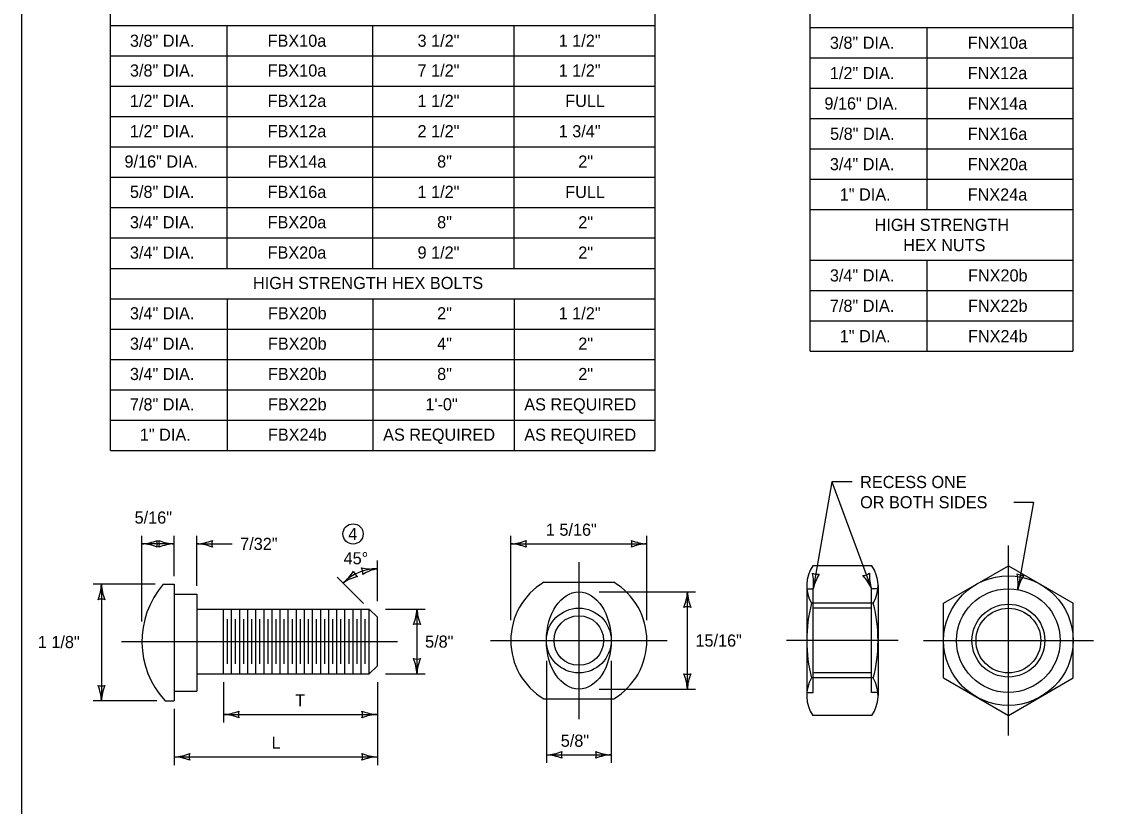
# Model space of a CAD drawing. Extents: x 49991.4 to 50021, y 49987.6 to 50011.4.
# Drawn here: x 49999.38 to 50004.77, y 49992.68 to 49996.55 of the extents above; entities that cross this region are included whole.
import ezdxf

# ---------------------------------------------------------------- set-up
doc = ezdxf.new("R2010")
doc.units = 0
for name, color, linetype in [('Level 1', 7, 'Continuous'), ('Level 2', 7, 'Continuous'), ('Level 3', 7, 'Continuous'), ('Level 4', 7, 'Continuous'), ('Level 5', 7, 'Continuous')]:
    doc.layers.add(name, color=color, linetype=linetype)

msp = doc.modelspace()

# ---------------------------------------------------------------- linework, layer by layer
at = {"layer": 'Level 1'}
for p, q in [((50003.5823, 49993.8656), (50003.2903, 49993.8656)), ((50003.9362, 49993.6809), (50004.2562, 49993.8656)), ((50004.2562, 49993.8656), (50004.5762, 49993.6809)), ((50000.082, 49993.7743), (50000.1366, 49993.7743)), ((50000.1366, 49993.7743), (50000.1366, 49993.1983)), ((50001.9614, 49993.7844), (50002.3076, 49993.7844)), ((50000.1366, 49993.7263), (50000.2486, 49993.7263)), ((50000.2486, 49993.7263), (50000.2486, 49993.2463)), ((50003.2603, 49993.768), (50003.2603, 49993.2242)), ((50003.6123, 49993.768), (50003.6123, 49993.2242)), ((50003.5888, 49993.6809), (50003.2838, 49993.6809)), ((50003.9362, 49993.3114), (50003.9362, 49993.6809)), ((50004.5762, 49993.3114), (50004.5762, 49993.6809)), ((50000.2486, 49993.6512), (50001.0997, 49993.6512)), ((50000.3797, 49993.3312), (50000.3797, 49993.6512)), ((50000.4197, 49993.3312), (50000.4197, 49993.6512)), ((50000.4597, 49993.3312), (50000.4597, 49993.6512)), ((50000.4997, 49993.3312), (50000.4997, 49993.6512)), ((50000.5397, 49993.3312), (50000.5397, 49993.6512)), ((50000.5797, 49993.3312), (50000.5797, 49993.6512)), ((50000.6197, 49993.3312), (50000.6197, 49993.6512)), ((50000.6597, 49993.3312), (50000.6597, 49993.6512)), ((50000.6997, 49993.3312), (50000.6997, 49993.6512)), ((50000.7397, 49993.3312), (50000.7397, 49993.6512)), ((50000.7797, 49993.3312), (50000.7797, 49993.6512)), ((50000.8197, 49993.3312), (50000.8197, 49993.6512)), ((50000.8597, 49993.3312), (50000.8597, 49993.6512)), ((50000.8997, 49993.3312), (50000.8997, 49993.6512)), ((50000.9397, 49993.3312), (50000.9397, 49993.6512)), ((50000.9797, 49993.3312), (50000.9797, 49993.6512)), ((50001.0197, 49993.3312), (50001.0197, 49993.6512)), ((50001.0597, 49993.3312), (50001.0597, 49993.6512)), ((50001.0997, 49993.3312), (50001.0997, 49993.6512)), ((50001.0997, 49993.6512), (50001.1397, 49993.6112)), ((50001.1397, 49993.3712), (50001.1397, 49993.6112)), ((50000.3997, 49993.3812), (50000.3997, 49993.6012)), ((50000.4397, 49993.3812), (50000.4397, 49993.6012)), ((50000.4797, 49993.3812), (50000.4797, 49993.6012)), ((50000.5197, 49993.3812), (50000.5197, 49993.6012)), ((50000.5597, 49993.3812), (50000.5597, 49993.6012)), ((50000.5997, 49993.3812), (50000.5997, 49993.6012)), ((50000.6397, 49993.3812), (50000.6397, 49993.6012)), ((50000.6797, 49993.3812), (50000.6797, 49993.6012)), ((50000.7197, 49993.3812), (50000.7197, 49993.6012)), ((50000.7597, 49993.3812), (50000.7597, 49993.6012)), ((50000.7997, 49993.3812), (50000.7997, 49993.6012)), ((50000.8397, 49993.3812), (50000.8397, 49993.6012)), ((50000.8797, 49993.3812), (50000.8797, 49993.6012)), ((50000.9197, 49993.3812), (50000.9197, 49993.6012)), ((50000.9597, 49993.3812), (50000.9597, 49993.6012)), ((50000.9997, 49993.3812), (50000.9997, 49993.6012)), ((50001.0397, 49993.3812), (50001.0397, 49993.6012)), ((50001.0797, 49993.3812), (50001.0797, 49993.6012)), ((50001.0997, 49993.3312), (50001.1397, 49993.3712)), ((50000.2486, 49993.3312), (50001.0997, 49993.3312)), ((50003.5888, 49993.3114), (50003.2838, 49993.3114)), ((50003.9362, 49993.3114), (50004.2562, 49993.1266)), ((50004.2562, 49993.1266), (50004.5762, 49993.3114)), ((50000.1366, 49993.2463), (50000.2486, 49993.2463)), ((50000.0908, 49993.1983), (50000.1366, 49993.1983)), ((50001.9614, 49993.2084), (50002.3076, 49993.2084)), ((50003.5823, 49993.1266), (50003.2903, 49993.1266))]:
    msp.add_line(p, q, dxfattribs=at)
msp.add_lwpolyline([(49999.3835, 49998.9992), (50016.7501, 49998.9992), (50016.7501, 49987.7988), (49999.3835, 49987.7988)], close=True, dxfattribs=at)
for centre, radius in [((50004.2562, 49993.4961), 0.32), ((50004.2562, 49993.4961), 0.256), ((50002.1345, 49993.4964), 0.16), ((50002.1345, 49993.4964), 0.1225), ((50004.2562, 49993.4961), 0.16)]:
    msp.add_circle(centre, radius, dxfattribs=at)
for centre, radius, start, end in [((50003.434, 49993.768), 0.1737, 145.8194, 210.1292), ((50003.4386, 49993.768), 0.1737, 329.8708, 34.1806), ((50000.4094, 49993.4912), 0.4328, 139.1488, 222.5919), ((50002.1345, 49993.4964), 0.336, 121.0027, 238.9973), ((50002.1345, 49993.4964), 0.336, 301.0027, 58.9973), ((50003.9993, 49993.4961), 0.739, 165.5224, 194.4774), ((50002.8733, 49993.4961), 0.739, 345.5226, 14.4776), ((50003.434, 49993.2242), 0.1737, 149.8708, 214.1806), ((50003.4386, 49993.2242), 0.1737, 325.8194, 30.1292)]:
    msp.add_arc(centre, radius, start, end, dxfattribs=at)
msp.add_ellipse((50002.1345, 49993.4964), major_axis=(0, 0.24), ratio=0.666667, dxfattribs=at)
at = {"layer": 'Level 2'}
for p, q in [((49999.8208, 49994.436), (49999.8208, 49996.936)), ((50002.5121, 49994.436), (50002.5121, 49996.936)), ((50003.2779, 49994.926), (50003.2779, 49996.936)), ((50004.5745, 49996.936), (50004.5745, 49994.926)), ((49999.8208, 49996.536), (50002.5121, 49996.536)), ((50000.3975, 49995.336), (50000.3975, 49996.536)), ((50001.1175, 49995.336), (50001.1175, 49996.536)), ((50001.8148, 49995.336), (50001.8148, 49996.536)), ((50003.2779, 49996.526), (50004.5745, 49996.526)), ((50003.2779, 49996.526), (50004.5745, 49996.526)), ((50003.8545, 49995.626), (50003.8545, 49996.526)), ((49999.8208, 49996.386), (50002.5121, 49996.386)), ((50003.2779, 49996.376), (50004.5745, 49996.376)), ((49999.8208, 49996.236), (50002.5121, 49996.236)), ((50003.2779, 49996.226), (50004.5745, 49996.226)), ((49999.8208, 49996.086), (50002.5121, 49996.086)), ((50003.2779, 49996.076), (50004.5745, 49996.076)), ((49999.8208, 49995.936), (50002.5121, 49995.936)), ((50003.2779, 49995.926), (50004.5745, 49995.926)), ((49999.8208, 49995.786), (50002.5121, 49995.786)), ((50003.2779, 49995.776), (50004.5745, 49995.776)), ((49999.8208, 49995.636), (50002.5121, 49995.636)), ((50003.2779, 49995.626), (50004.5745, 49995.626)), ((49999.8208, 49995.486), (50002.5121, 49995.486)), ((49999.8208, 49995.336), (50002.5121, 49995.336)), ((50003.2779, 49995.376), (50004.5745, 49995.376)), ((50003.8545, 49994.926), (50003.8545, 49995.376)), ((50003.2779, 49995.226), (50004.5745, 49995.226)), ((49999.8208, 49995.186), (50002.5121, 49995.186)), ((50000.3975, 49995.186), (50000.3975, 49994.436)), ((50001.1175, 49995.186), (50001.1175, 49994.436)), ((50001.8148, 49995.186), (50001.8148, 49994.436)), ((50003.2779, 49995.076), (50004.5745, 49995.076)), ((49999.8208, 49995.036), (50002.5121, 49995.036)), ((50003.2779, 49994.926), (50004.5745, 49994.926)), ((49999.8208, 49994.886), (50002.5121, 49994.886)), ((49999.8208, 49994.736), (50002.5121, 49994.736)), ((49999.8208, 49994.586), (50002.5121, 49994.586)), ((49999.8208, 49994.436), (50002.5121, 49994.436))]:
    msp.add_line(p, q, dxfattribs=at)
msp.add_circle((50001.0195, 49994.0231), 0.05, dxfattribs=at)
at = {"layer": 'Level 3'}
for p, q in [((50003.3839, 49994.28), (50003.2923, 49993.7521)), ((50003.4839, 49994.28), (50003.3839, 49994.28)), ((50003.3839, 49994.28), (50003.5803, 49993.7521)), ((50004.2827, 49994.18), (50004.3808, 49994.18)), ((50004.3808, 49994.18), (50004.3021, 49993.748)), ((49999.9766, 49993.5912), (49999.9766, 49994.0143)), ((50000.1366, 49993.8143), (50000.1366, 49994.0143)), ((50000.2486, 49993.7663), (50000.2486, 49994.0143)), ((50001.7985, 49993.5964), (50001.7985, 49994.0143)), ((50002.4705, 49993.5964), (50002.4705, 49994.0143)), ((50000.1366, 49993.9743), (49999.9766, 49993.9743)), ((50000.2486, 49993.9743), (50000.422, 49993.9743)), ((50001.7985, 49993.9743), (50002.4705, 49993.9743)), ((50001.1397, 49993.6912), (50001.1397, 49993.8912)), ((50000.042, 49993.7743), (49999.7366, 49993.7743)), ((49999.7766, 49993.7743), (49999.7766, 49993.1983)), ((50001.0714, 49993.6795), (50000.9417, 49993.8092)), ((50002.2345, 49993.7364), (50002.7105, 49993.7364)), ((50002.6705, 49993.2564), (50002.6705, 49993.7364)), ((50001.1797, 49993.6512), (50001.3752, 49993.6512)), ((50001.3352, 49993.6512), (50001.3352, 49993.3312)), ((50001.9745, 49993.3964), (50001.9745, 49992.8913)), ((50002.2945, 49993.3964), (50002.2945, 49992.8913)), ((50000.3797, 49993.2912), (50000.3797, 49993.0912)), ((50001.1397, 49993.2912), (50001.1397, 49992.8812)), ((50001.1797, 49993.3312), (50001.3752, 49993.3312)), ((50002.2345, 49993.2564), (50002.7105, 49993.2564)), ((50000.0508, 49993.1983), (49999.7366, 49993.1983)), ((50000.1366, 49993.1583), (50000.1366, 49992.8812)), ((50000.3797, 49993.1312), (50001.1397, 49993.1312)), ((50000.1366, 49992.9212), (50001.1397, 49992.9212)), ((50001.9745, 49992.9313), (50002.2945, 49992.9313))]:
    msp.add_line(p, q, dxfattribs=at)
for centre, radius, start, end in [((49999.9651, 49994.207), 0.233, 272.8273, 292.0772), ((50000.1048, 49993.9743), 0.0548, 162.1388, 197.8612), ((50000.1458, 49994.1964), 0.2223, 247.456, 267.6395), ((50000.0084, 49993.9743), 0.0548, 342.1388, 17.8612), ((50000.2371, 49994.207), 0.233, 272.8273, 292.0772), ((50000.3768, 49993.9743), 0.0548, 162.1388, 197.8612), ((50001.7893, 49994.1964), 0.2223, 272.3605, 292.544), ((50001.9267, 49993.9743), 0.0548, 162.1388, 197.8612), ((50002.3423, 49993.9743), 0.0548, 342.1388, 17.8612), ((50002.482, 49994.207), 0.233, 247.9228, 267.1727), ((49999.9675, 49993.7522), 0.2223, 67.456, 87.6395), ((50000.1481, 49993.7416), 0.233, 92.8273, 112.0772), ((50000.2395, 49993.7522), 0.2223, 67.456, 87.6395), ((50001.787, 49993.7416), 0.233, 67.9228, 87.1727), ((50002.4796, 49993.7522), 0.2223, 92.3605, 112.544), ((50001.1397, 49993.6112), 0.24, 90, 135.0001), ((50000.8234, 49993.962), 0.233, 308.9887, 328.2385), ((50001.0735, 49993.8566), 0.0548, 198.3002, 234.0226), ((50001.1147, 49994.0721), 0.2223, 256.2719, 276.4554), ((50001.013, 49993.8316), 0.0548, 350.9547, 26.6771), ((50001.1867, 49993.623), 0.233, 101.6432, 120.8931), ((50003.3142, 49993.8784), 0.0548, 242.2974, 278.0198), ((50003.061, 49993.7806), 0.233, 352.9859, 12.2358), ((50003.5096, 49993.7051), 0.2223, 147.6146, 167.7981), ((50003.5356, 49993.8723), 0.0548, 272.5357, 308.2581), ((50003.7917, 49993.821), 0.2223, 177.8529, 198.0364), ((50004.3251, 49993.8741), 0.0548, 241.8087, 277.5311), ((50004.0711, 49993.7784), 0.233, 352.4972, 11.747), ((49999.5545, 49993.7835), 0.2223, 337.456, 357.6395), ((50000.0093, 49993.7858), 0.233, 182.8273, 202.0771), ((50001.0936, 49993.5962), 0.2223, 103.6174, 123.8009), ((50003.3662, 49993.6602), 0.233, 23.2242, 42.4741), ((50004.519, 49993.6991), 0.2223, 147.1259, 167.3094), ((50002.4484, 49993.7456), 0.2223, 337.456, 357.6395), ((50002.9032, 49993.7479), 0.233, 182.8273, 202.0771), ((49999.7766, 49993.6461), 0.0548, 72.1388, 107.8611), ((50002.6705, 49993.6082), 0.0548, 72.1388, 107.8611), ((50001.113, 49993.6604), 0.2223, 337.456, 357.6395), ((50001.5679, 49993.6627), 0.233, 182.8273, 202.0771), ((50001.3352, 49993.523), 0.0548, 72.1388, 107.8611), ((50001.3352, 49993.4594), 0.0548, 252.1388, 287.8611), ((50001.1025, 49993.3197), 0.233, 2.8273, 22.0771), ((50001.5573, 49993.3221), 0.2223, 157.456, 177.6395), ((50002.6705, 49993.3846), 0.0548, 252.1388, 287.8611), ((50002.4378, 49993.2449), 0.233, 2.8273, 22.0771), ((50002.8926, 49993.2473), 0.2223, 157.456, 177.6395), ((49999.7766, 49993.3265), 0.0548, 252.1388, 287.8611), ((49999.5439, 49993.1868), 0.233, 2.8273, 22.0771), ((49999.9987, 49993.1891), 0.2223, 157.456, 177.6395), ((50000.3682, 49993.3639), 0.233, 272.8273, 292.0772), ((50000.3705, 49992.9091), 0.2223, 67.456, 87.6395), ((50000.5079, 49993.1312), 0.0548, 162.1388, 197.8612), ((50001.1488, 49993.3534), 0.2223, 247.456, 267.6395), ((50001.0114, 49993.1312), 0.0548, 342.1388, 17.8612), ((50001.1511, 49992.8985), 0.233, 92.8273, 112.0772), ((50000.1251, 49993.1539), 0.233, 272.8273, 292.0772), ((50000.1275, 49992.6991), 0.2223, 67.456, 87.6395), ((50000.2648, 49992.9212), 0.0548, 162.1388, 197.8612), ((50001.1488, 49993.1434), 0.2223, 247.456, 267.6395), ((50001.0114, 49992.9212), 0.0548, 342.1388, 17.8612), ((50001.1511, 49992.6885), 0.233, 92.8273, 112.0772), ((50001.9653, 49993.1535), 0.2223, 272.3605, 292.544), ((50001.963, 49992.6986), 0.233, 67.9228, 87.1727), ((50002.1027, 49992.9313), 0.0548, 162.1388, 197.8612), ((50002.1663, 49992.9313), 0.0548, 342.1388, 17.8612), ((50002.306, 49993.1641), 0.233, 247.9228, 267.1727), ((50002.3036, 49992.7092), 0.2223, 92.3605, 112.544)]:
    msp.add_arc(centre, radius, start, end, dxfattribs=at)
at = {"layer": 'Level 4'}
for p, q in [((50003.2603, 49993.7521), (50003.2923, 49993.7521)), ((50003.2923, 49993.2401), (50003.2923, 49993.7521)), ((50003.5803, 49993.2401), (50003.5803, 49993.7521)), ((50003.6123, 49993.7521), (50003.5803, 49993.7521)), ((50003.5803, 49993.6561), (50003.2923, 49993.6561)), ((50003.5803, 49993.3361), (50003.2923, 49993.3361)), ((50003.2603, 49993.2401), (50003.2923, 49993.2401)), ((50003.6123, 49993.2401), (50003.5803, 49993.2401))]:
    msp.add_line(p, q, dxfattribs=at)
msp.add_circle((50004.2562, 49993.4961), 0.18, dxfattribs=at)
at = {"layer": 'Level 5'}
for p, q in [((50004.2562, 49993.0266), (50004.2562, 49993.9656)), ((50002.1345, 49993.8844), (50002.1345, 49993.1084)), ((49999.8766, 49993.4912), (50001.2397, 49993.4912)), ((50001.6985, 49993.4964), (50002.5705, 49993.4964)), ((50003.7123, 49993.4961), (50003.1603, 49993.4961)), ((50003.8362, 49993.4961), (50004.6762, 49993.4961))]:
    msp.add_line(p, q, dxfattribs=at)

# ---------------------------------------------------------------- texts
at = {"layer": 'Level 2'}
for s, p in [('3/8" DIA.', (49999.9175, 49996.431)), ('FBX10a', (50000.5974, 49996.431)), ('3 1/2"', (50001.338, 49996.431)), ('1 1/2"', (50002.0351, 49996.431)), ('3/8" DIA.', (50003.3745, 49996.421)), ('FNX10a', (50004.055, 49996.421)), ('3/8" DIA.', (49999.9175, 49996.284)), ('FBX10a', (50000.5974, 49996.284)), ('7 1/2"', (50001.338, 49996.284)), ('1 1/2"', (50002.0351, 49996.2837)), ('1/2" DIA.', (50003.3745, 49996.271)), ('FNX12a', (50004.055, 49996.271)), ('1/2" DIA.', (49999.9175, 49996.134)), ('FBX12a', (50000.5974, 49996.134)), ('1 1/2"', (50001.338, 49996.134)), ('FULL', (50002.0673, 49996.1337)), ('9/16" DIA.', (50003.3475, 49996.121)), ('FNX14a', (50004.055, 49996.121)), ('1/2" DIA.', (49999.9175, 49995.984)), ('FBX12a', (50000.5974, 49995.984)), ('2 1/2"', (50001.338, 49995.984)), ('1 3/4"', (50002.0351, 49995.9837)), (' 5/8" DIA.', (50003.3534, 49995.971)), ('FNX16a', (50004.055, 49995.971)), ('9/16" DIA.', (49999.8906, 49995.834)), ('FBX14a', (50000.5974, 49995.834)), ('8"', (50001.4347, 49995.834)), ('2"', (50002.1319, 49995.8337)), ('3/4" DIA.', (50003.3745, 49995.821)), ('FNX20a', (50004.055, 49995.821)), ('5/8" DIA.', (49999.9175, 49995.6839)), ('FBX16a', (50000.5974, 49995.684)), ('1 1/2"', (50001.338, 49995.684)), ('FULL', (50002.0673, 49995.6837)), ('1" DIA.', (50003.4232, 49995.671)), ('FNX24a', (50004.055, 49995.671)), ('3/4" DIA.', (49999.9175, 49995.5339)), ('FBX20a', (50000.5974, 49995.534)), ('8"', (50001.4348, 49995.534)), ('2"', (50002.1319, 49995.5337)), ('HIGH STRENGTH', (50003.5954, 49995.521)), ('3/4" DIA.', (49999.9175, 49995.3839)), ('FBX20a', (50000.5974, 49995.384)), ('9 1/2"', (50001.338, 49995.384)), ('2"', (50002.1319, 49995.3837)), ('HEX NUTS', (50003.7369, 49995.421)), ('3/4" DIA.', (50003.3745, 49995.271)), ('FNX20b', (50004.0566, 49995.271)), ('HIGH STRENGTH HEX BOLTS', (50000.5252, 49995.2337)), ('7/8" DIA.', (50003.3745, 49995.121)), ('FNX22b', (50004.0566, 49995.121)), ('3/4" DIA.', (49999.9175, 49995.0839)), ('FBX20b', (50000.5991, 49995.084)), ('2"', (50001.4348, 49995.084)), ('1 1/2"', (50002.0351, 49995.0837)), ('1" DIA.', (50003.4232, 49994.971)), ('FNX24b', (50004.0566, 49994.971)), ('3/4" DIA.', (49999.9175, 49994.9339)), ('FBX20b', (50000.5991, 49994.934)), ('4"', (50001.4348, 49994.934)), ('2"', (50002.1319, 49994.9337)), ('3/4" DIA.', (49999.9175, 49994.7839)), ('FBX20b', (50000.5991, 49994.784)), ('8"', (50001.4348, 49994.784)), ('2"', (50002.1319, 49994.7837)), ('7/8" DIA.', (49999.9175, 49994.6339)), ('FBX22b', (50000.5991, 49994.634)), ('1\'-0"', (50001.3766, 49994.634)), ('AS REQUIRED', (50001.8651, 49994.6337)), ('1" DIA.', (49999.9663, 49994.4839)), ('FBX24b', (50000.5991, 49994.484)), ('AS REQUIRED', (50001.168, 49994.484)), ('AS REQUIRED', (50001.8651, 49994.4837)), ('RECESS ONE', (50003.5239, 49994.25)), ('OR BOTH SIDES', (50003.5239, 49994.15)), ('5/16"', (49999.9406, 49994.0743)), ('4', (50000.9955, 49993.9931)), (' 1 5/16"', (50001.9495, 49994.0143)), ('7/32"', (50000.462, 49993.9443)), ('45°', (50000.9728, 49993.8731)), ('1 1/8"', (49999.4625, 49993.459)), ('5/8"', (50001.3752, 49993.4612)), ('15/16"', (50002.7105, 49993.4664)), ('T', (50000.7336, 49993.1712)), ('L', (50000.6169, 49992.9612)), ('5/8"', (50002.0454, 49992.9713))]:
    msp.add_text(s, height=0.06, dxfattribs=at).set_placement(p)

doc.saveas('drawing.dxf')
